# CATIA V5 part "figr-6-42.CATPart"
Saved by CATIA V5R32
Part number: Part1
Bounding box of the stored display mesh (mm): x -40.3 to 40.3, y -45.975 to 45.975, z 0 to 40
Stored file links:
  D:\PROJECTS\Project 2022\CATIA V5 6R 2022\Resources\Part Files\c06_catia_v5_6r2022_prt\figr-6-42.CATPart
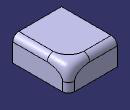
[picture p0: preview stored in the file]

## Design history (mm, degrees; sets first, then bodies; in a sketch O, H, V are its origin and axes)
Body1 (main body)
  Sketch1 on xy-plane, origin (0, 0, 0), H (1, 0, 0), V (0, 1, 0)
    line L1 (-40.2998, 45.9753) -> (40.2998, 45.9753)
    line L2 (40.2998, 45.9753) -> (40.2998, -45.9753)
    line L3 (40.2998, -45.9753) -> (-40.2998, -45.9753)
    line L4 (-40.2998, -45.9753) -> (-40.2998, 45.9753)
    axis line L5 (40.2998, -45.9753) -> (-40.2998, 45.9753)
    horizontal: L1 H, L3 H
    vertical: L2 V, L4 V
    midpoint: O L5
  Pad1: profile Sketch1, direction (0, 0, 1), length 40
  Fillet1: radius 10, on edge [face of Pad1 | face of Pad1] (x3)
